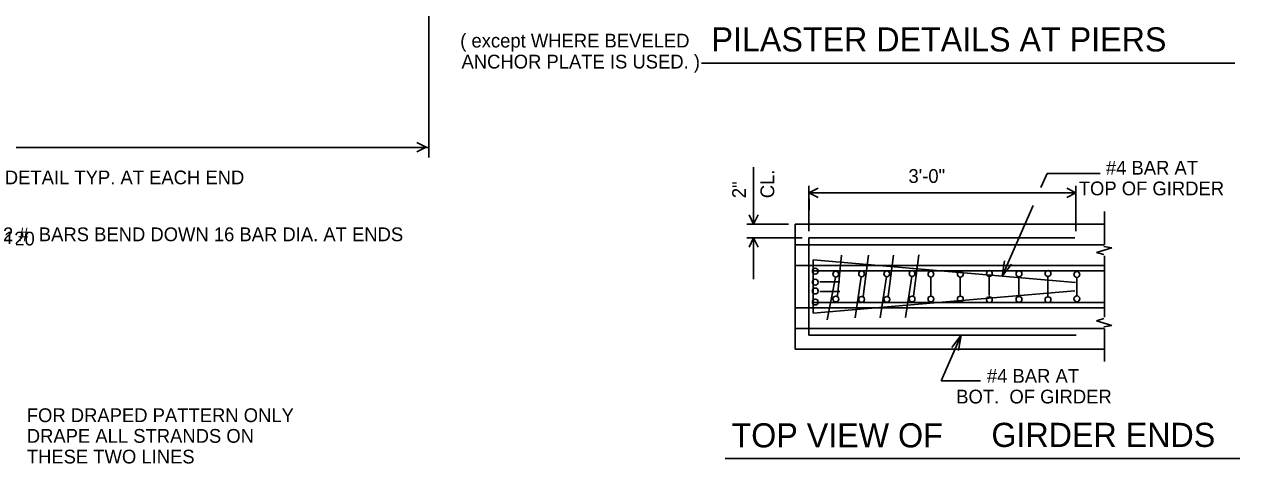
# Model space of a CAD drawing. Extents: x 1005 to 1123, y 2008 to 2074.
# Drawn here: x 1047.9 to 1077.32, y 2040.42 to 2051.04 of the extents above; entities that cross this region are included whole.
import ezdxf

# ---------------------------------------------------------------- set-up
doc = ezdxf.new("R2010")
doc.units = 0
for name, color, linetype in [('Level 2', 7, 'Continuous'), ('Level 6', 7, 'Continuous'), ('Level 60', 7, 'Continuous'), ('Level 7', 7, 'Continuous')]:
    doc.layers.add(name, color=color, linetype=linetype)

msp = doc.modelspace()

# ---------------------------------------------------------------- linework, layer by layer
at = {"layer": 'Level 2'}
for p, q in [((1057.695, 2047.823), (1057.695, 2052.087)), ((1018.361, 2048.066), (1057.695, 2048.066)), ((1065.555, 2046.209), (1065.555, 2047.587)), ((1072.658, 2047.432), (1072.511, 2047.097)), ((1073.942, 2047.432), (1072.658, 2047.432)), ((1066.896, 2046.043), (1066.896, 2047.136)), ((1073.357, 2046.043), (1073.357, 2047.136)), ((1066.896, 2046.969), (1073.357, 2046.969)), ((1066.902, 2046.55), (1066.902, 2046.823)), ((1072.32, 2046.663), (1071.568, 2044.953)), ((1074.046, 2045.717), (1074.046, 2046.514)), ((1066.396, 2046.209), (1065.389, 2046.209)), ((1066.562, 2044.699), (1066.562, 2046.209)), ((1074.046, 2046.209), (1066.562, 2046.209)), ((1066.729, 2045.876), (1065.389, 2045.876)), ((1065.555, 2044.876), (1065.555, 2045.876)), ((1066.562, 2045.709), (1074.046, 2045.709)), ((1066.896, 2045.876), (1073.332, 2045.876)), ((1066.896, 2044.699), (1066.896, 2045.876)), ((1073.851, 2045.522), (1074.225, 2045.636)), ((1074.225, 2045.636), (1074.03, 2045.669)), ((1066.993, 2045.344), (1073.349, 2044.801)), ((1066.993, 2044.699), (1066.993, 2045.344)), ((1067.583, 2044.473), (1067.679, 2045.459)), ((1068.204, 2044.462), (1068.333, 2045.459)), ((1068.814, 2044.462), (1068.943, 2045.459)), ((1069.425, 2044.47), (1069.554, 2045.467)), ((1071.568, 2044.953), (1071.631, 2045.319)), ((1074.03, 2045.474), (1073.851, 2045.522)), ((1074.046, 2044.699), (1074.046, 2045.441)), ((1066.562, 2045.209), (1074.046, 2045.209)), ((1067.001, 2045.083), (1068.171, 2045.083)), ((1068.188, 2045.083), (1074.046, 2045.083)), ((1071.568, 2044.953), (1071.796, 2045.246)), ((1067.156, 2044.815), (1067.643, 2044.815)), ((1067.336, 2043.894), (1067.54, 2044.923)), ((1068.011, 2043.948), (1068.161, 2044.934)), ((1068.622, 2043.948), (1068.772, 2044.934)), ((1069.232, 2043.956), (1069.382, 2044.941)), ((1069.846, 2044.475), (1069.846, 2044.929)), ((1070.558, 2044.475), (1070.558, 2044.929)), ((1071.26, 2044.487), (1071.26, 2044.945)), ((1071.972, 2044.463), (1071.972, 2044.947)), ((1072.674, 2044.451), (1072.674, 2044.934)), ((1073.378, 2044.475), (1073.378, 2044.921)), ((1066.562, 2044.699), (1066.562, 2043.189)), ((1066.896, 2044.699), (1066.896, 2043.523)), ((1066.993, 2044.699), (1066.993, 2044.055)), ((1066.993, 2044.055), (1073.333, 2044.596)), ((1067.156, 2044.583), (1067.643, 2044.583)), ((1074.046, 2044.699), (1074.046, 2043.958)), ((1066.562, 2044.189), (1074.046, 2044.189)), ((1067.001, 2044.315), (1068.171, 2044.315)), ((1068.188, 2044.315), (1074.046, 2044.315)), ((1074.03, 2043.925), (1073.851, 2043.876)), ((1073.851, 2043.876), (1074.225, 2043.763)), ((1066.562, 2043.689), (1074.046, 2043.689)), ((1074.225, 2043.763), (1074.03, 2043.73)), ((1074.046, 2043.681), (1074.046, 2042.885)), ((1066.896, 2043.523), (1073.366, 2043.523)), ((1070.094, 2042.418), (1070.58, 2043.523)), ((1070.58, 2043.523), (1070.352, 2043.229)), ((1070.58, 2043.523), (1070.517, 2043.157)), ((1066.562, 2043.189), (1074.046, 2043.189)), ((1071.046, 2042.418), (1070.094, 2042.418)), ((1064.869, 2040.542), (1077.32, 2040.542))]:
    msp.add_line(p, q, dxfattribs=at)
for points in [[(1057.408, 2047.959), (1057.631, 2048.07), (1057.408, 2048.181)], [(1067.118, 2046.858), (1066.896, 2046.969), (1067.118, 2047.081)], [(1073.134, 2046.858), (1073.357, 2046.969), (1073.134, 2047.081)], [(1065.444, 2046.432), (1065.555, 2046.209), (1065.666, 2046.432)], [(1065.444, 2045.654), (1065.555, 2045.876), (1065.666, 2045.654)]]:
    msp.add_lwpolyline(points, dxfattribs=at)
for centre in [(1067.048, 2045.073), (1067.544, 2045), (1068.17, 2045.008), (1068.78, 2045.008), (1069.39, 2045.016), (1069.847, 2045), (1070.559, 2045), (1071.262, 2045.016), (1071.978, 2045.008), (1072.681, 2045.016), (1073.38, 2044.992), (1067.048, 2044.805), (1067.048, 2044.594), (1067.544, 2044.399), (1068.17, 2044.391), (1068.78, 2044.391), (1069.39, 2044.399), (1069.847, 2044.399), (1070.559, 2044.399), (1071.262, 2044.383), (1071.978, 2044.391), (1072.681, 2044.383), (1073.38, 2044.406), (1067.048, 2044.326)]:
    msp.add_circle(centre, 0.0708, dxfattribs=at)
at = {"layer": 'Level 7'}
msp.add_line((1064.295, 2050.106), (1077.206, 2050.106), dxfattribs=at)

# ---------------------------------------------------------------- texts
at = {"layer": 'Level 2'}
for s, height, p in [('#4 BAR AT', 0.3333, (1074.082, 2047.407)), ('DETAIL TYP. AT EACH END', 0.33333, (1047.432, 2047.173)), ('3\'-0"', 0.3333, (1069.303, 2047.207)), ('   TOP OF GIRDER', 0.33333, (1073.054, 2046.907)), ('2 #  BARS BEND DOWN 16 BAR DIA. AT ENDS ', 0.33333, (1047.389, 2045.797)), ('#4 BAR AT', 0.3333, (1071.202, 2042.374)), ('   BOT.  OF GIRDER', 0.33333, (1070.088, 2041.874)), ('FOR DRAPED PATTERN ONLY', 0.33333, (1047.964, 2041.423)), ('DRAPE ALL STRANDS ON', 0.33333, (1047.964, 2040.923)), ('TOP VIEW OF', 0.58333, (1065.021, 2040.812)), (' GIRDER ENDS', 0.58333, (1071.094, 2040.823)), ('THESE TWO LINES', 0.33333, (1047.964, 2040.423))]:
    msp.add_text(s, height=height, dxfattribs=at).set_placement(p)
for s, p in [('CL.', (1066.055, 2046.837)), ('2"', (1065.37, 2046.837))]:
    msp.add_text(s, height=0.3333, rotation=90, dxfattribs=at).set_placement(p)
at = {"layer": 'Level 6'}
for s, p in [('( except WHERE BEVELED', (1058.455, 2050.481)), ('ANCHOR PLATE IS USED. )', (1058.486, 2049.973))]:
    msp.add_text(s, height=0.33333, dxfattribs=at).set_placement(p)
at = {"layer": 'Level 60'}
msp.add_text('120', height=0.3333, dxfattribs=at).set_placement((1047.413, 2045.694))
at = {"layer": 'Level 7'}
msp.add_text('PILASTER DETAILS AT PIERS', height=0.58333, dxfattribs=at).set_placement((1064.536, 2050.385))

doc.saveas('drawing.dxf')
